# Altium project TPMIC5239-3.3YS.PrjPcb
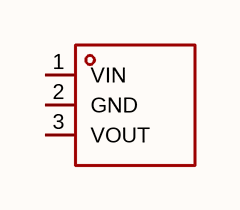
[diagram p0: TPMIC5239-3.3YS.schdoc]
1 sheet, 1 parts. Net scope: global (net labels, ports and power ports of the same name join across sheets).

## Sheet TPMIC5239-3.3YS.schdoc
size 127 x 101 mm

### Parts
U?  tpmic5239-3.3ys  [SOT-223-3_L6.5-W3.4-P2.30-LS7.0-BR-1]  (value not drawn)

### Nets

Not connected (* = marked no-connect by the designer): U? 1(VIN) 2(GND) 3(VOUT)

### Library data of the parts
U? = tpmic5239-3.3ys: 输出类型:固定;工作电压:28V;输出电压:3.3V;输出电流:300mA;电源纹波抑制比(PSRR):70dB@(1kHz);输出极性:正极;; Manufacturer: TECH PUBLIC(台舟); AddInBom: yes; ModelId: 0a360ebfdb9248a182f670f5fd8a68d2; ModelTransform: 275.59,255.905,0,0,0,0,-3.937,0,0; Output Type: 固定; Voltage - Supply: 28V; Output Voltage: 3.3V; Output Current: 300mA; standby current: 1.5uA; Output Configuration: 正极; Number of Outputs: 1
